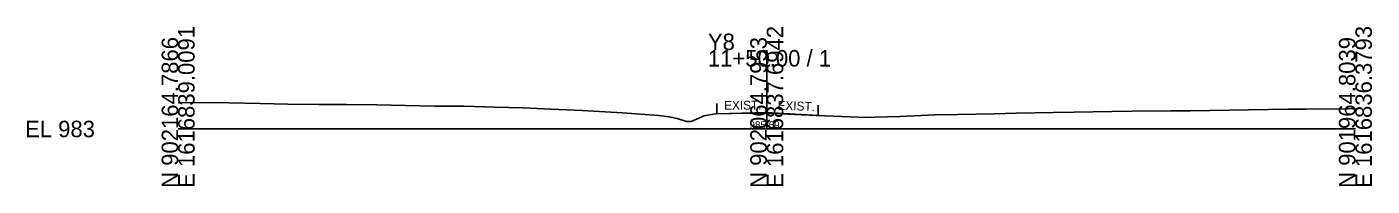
# Model space of a CAD drawing. Extents: x -26 to 1403, y -10 to 3025.
# Drawn here: x -25.7 to 202.8, y 1490.3 to 1517.3 of the extents above; entities that cross this region are included whole.
import ezdxf

# ---------------------------------------------------------------- set-up
doc = ezdxf.new("R2010")
doc.units = 0
for name, color, linetype in [('Exist Cross Section Cell', 7, 'Continuous'), ('Exist XS Center Line Elevation Label', 7, 'Continuous'), ('Exist XS Ground Line', 7, 'Continuous'), ('Prop XS EOT Tick Mark', 7, 'Continuous'), ('Prop XS Finish Grade Pavement', 7, 'Continuous'), ('Prop XS SE Text', 7, 'Continuous')]:
    doc.layers.add(name, color=color, linetype=linetype)

msp = doc.modelspace()

# ---------------------------------------------------------------- linework, layer by layer
at = {"layer": 'Exist Cross Section Cell'}
for p, q in [((100, 1500), (100, 1513.4)), ((0, 1500), (100, 1500)), ((100, 1500), (200, 1500))]:
    msp.add_line(p, q, dxfattribs=at)
at = {"layer": 'Exist XS Ground Line'}
for p, q in [((0, 1504.46), (4.15, 1504.47)), ((4.15, 1504.47), (8.62, 1504.45)), ((8.62, 1504.45), (14.02, 1504.34)), ((14.02, 1504.34), (18.62, 1504.23)), ((18.62, 1504.23), (23.89, 1504.16)), ((23.89, 1504.16), (28.62, 1504.16)), ((28.62, 1504.16), (33.77, 1504.09)), ((33.77, 1504.09), (38.62, 1503.99)), ((38.62, 1503.99), (43.64, 1503.87)), ((43.64, 1503.87), (48.62, 1503.88)), ((48.62, 1503.88), (53.74, 1503.72)), ((53.74, 1503.72), (58.62, 1503.57)), ((58.62, 1503.57), (63.38, 1503.38)), ((63.38, 1503.38), (68.63, 1503.11)), ((68.63, 1503.11), (75.52, 1502.75)), ((75.52, 1502.75), (81.69, 1502.3)), ((81.69, 1502.3), (83.41, 1502.04)), ((83.41, 1502.04), (84.79, 1501.79)), ((84.79, 1501.79), (86.39, 1501.28)), ((87.14, 1501.28), (88.97, 1502.08)), ((88.97, 1502.08), (89.29, 1502.24)), ((89.29, 1502.24), (90.61, 1502.44)), ((90.61, 1502.44), (91.29, 1502.57)), ((91.29, 1502.57), (94.13, 1502.61)), ((94.13, 1502.61), (100.22, 1502.69)), ((100.22, 1502.69), (105.88, 1502.41)), ((105.88, 1502.41), (108.46, 1502.29)), ((108.46, 1502.29), (115.51, 1502.03)), ((115.51, 1502.03), (116.24, 1501.93)), ((116.24, 1501.93), (122.61, 1502.14)), ((122.61, 1502.14), (128.63, 1502.4)), ((128.63, 1502.4), (132.48, 1502.48)), ((132.48, 1502.48), (138.63, 1502.58)), ((138.63, 1502.58), (142.35, 1502.66)), ((142.35, 1502.66), (148.64, 1502.77)), ((148.64, 1502.77), (152.22, 1502.84)), ((152.22, 1502.84), (158.64, 1502.98)), ((158.64, 1502.98), (162.1, 1503.02)), ((162.1, 1503.02), (168.64, 1503.09)), ((168.64, 1503.09), (171.97, 1503.07)), ((171.97, 1503.07), (178.64, 1503.17)), ((178.64, 1503.17), (181.84, 1503.24)), ((181.84, 1503.24), (188.64, 1503.35)), ((188.64, 1503.35), (191.71, 1503.38)), ((191.71, 1503.38), (198.64, 1503.42)), ((198.64, 1503.42), (200, 1503.45)), ((86.39, 1501.28), (87.14, 1501.28))]:
    msp.add_line(p, q, dxfattribs=at)
at = {"layer": 'Prop XS EOT Tick Mark'}
for p, q in [((91.53, 1502.58), (91.53, 1504.33)), ((108.73, 1502.28), (108.73, 1504.03))]:
    msp.add_line(p, q, dxfattribs=at)
at = {"layer": 'Prop XS Finish Grade Pavement'}
for p in [(91.53, 1502.58), (108.73, 1502.28)]:
    msp.add_line(p, (100, 1502.82), dxfattribs=at)

# ---------------------------------------------------------------- texts
at = {"layer": 'Exist Cross Section Cell'}
for s, p in [('N 902164.7866', (0, 1490)), ('E 1616839.0091', (2.8, 1490)), ('N 902064.7953', (100, 1490)), ('E 1616837.6942', (102.8, 1490)), ('N 901964.8039', (200, 1490)), ('E 1616836.3793', (202.8, 1490))]:
    msp.add_text(s, height=2.8, rotation=90, dxfattribs=at).set_placement(p)
for s, p in [('Y8', (90, 1513.4)), ('11+50.00 / 1', (90, 1510.6)), ('EL 983', (-26, 1498.6))]:
    msp.add_text(s, height=2.8, dxfattribs=at).set_placement(p)
at = {"layer": 'Exist XS Center Line Elevation Label'}
msp.add_text('985.69', height=1.25, dxfattribs=at).set_placement((97.07, 1500.06))
at = {"layer": 'Prop XS SE Text'}
for rotation, p in [(0.5729, (92.76, 1503.25)), (358.1604, (101.81, 1503.26))]:
    msp.add_text('EXIST.', height=1.5, rotation=rotation, dxfattribs=at).set_placement(p)

doc.saveas('drawing.dxf')
